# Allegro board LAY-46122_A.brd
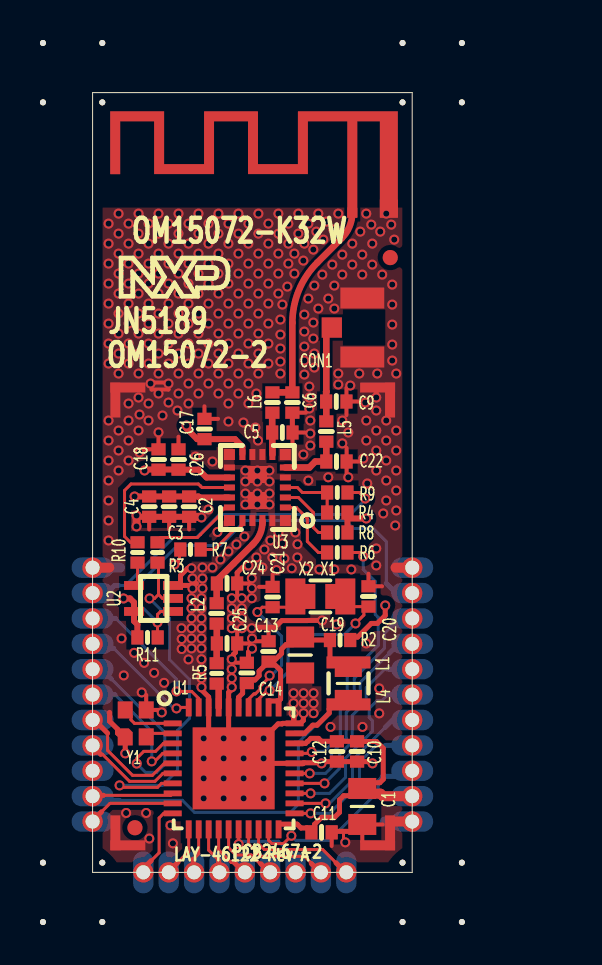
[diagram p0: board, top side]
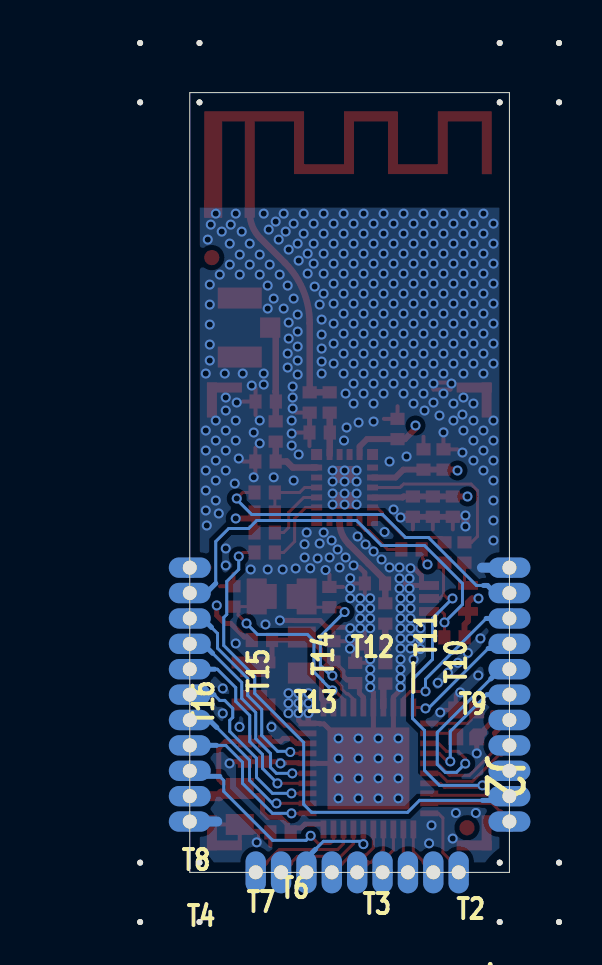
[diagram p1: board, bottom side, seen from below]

Outline 16 x 39 mm; copper layers: TOP, ANALOGUE GROUND, DIGITAL GROUND, BOTTOM. Coordinates in mm from the lower left corner of the outline.
Outline path: 0,39 0,0 16,0 16,39 0,39

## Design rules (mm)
constraint set DEFAULT: min track width 0.15
net group ALIM: nets N16830522 N16830755 VDD
net group DEFAUT: nets ANT_SEL CPS LA LB LNA_BYPASS N16830681 N16830775 N16832469 N16839365 N16842652 N16847933 N16848100 N16852723 N16876581 N169107841 PIO_0/SPI1_SCK PIO_1/SPI1_MISO PIO_2/SPI1_MOSI PIO_3/SPI1_SSELN0 PIO_4/RFTX PIO_5/RFRX PIO_6/PWM6-PD PIO_7/PWM7-PD PIO_8/USART0_TXD PIO_9/USART0_RXD PIO_10/I2C0_SCL PIO_11/I2C0_SDA PIO_12/SWCLK PIO_13/SWDIO PIO_14/ADC0 PIO_15/ADC1 PIO_16/SPIFI_CSN PIO_17/SPIFI_IO3 PIO_18/SPIFI_CLK PIO_19/SPIFI_IO0 PIO_20/SPIFI_IO2 PIO_21_SPIFI_IO1 RSTN
net group Z50: nets N16822568 N16830719 N16830729 N16831242 N16832450 N16869758 RF_PORT

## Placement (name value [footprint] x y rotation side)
1  BUBBLE-01  [BUBBLE_DIAM8]  23.5 23.5 0 top
ANT1  NC  [PCB_ANT_APPS]  13 33 0 top
C1  10uF  [C0805]  13.5 3.29 90 top
C2  1nF  [C0402]  4.83 18.29 270 top
C3  100nF  [C0402]  3.83 18.29 270 top
C4  4.7uF  [C0402]  2.83 18.29 270 top
C5  1pF  [C0402]  9.5 22 0 top
C6  1pF  [C0402]  10 23.5 270 top
C9  1pF  [C0402]  12.2 23.55 0 top
C10  100nF  [C0402]  13.24 6.04 90 top
C11  100nF  [C0402]  11.46 2 0 top
C12  47pF  [C0402]  12.23 6.04 90 top
C13  100nF  [C0402]  8.81 11.05 90 top
C14  47pF  [C0402]  7.72 9.97 90 top
C17  1nF  [C0402]  5.6 22.18 90 top
C18  100nF  [C0402]  3.3 20.65 90 top
C19  10uF  [C0805]  10.39 10.87 270 top
C20  NC  [C0402]  13.81 13.8 270 top
C21  NC  [C0402]  9.01 13.77 90 top
C22  1pF  [C0402]  12.21 20.55 0 top
C24  0.8pF  [C0402]  6.73 14.45 180 top
C25  2.0pF  [C0402]  6.73 11.45 180 top
C26  1nF  [C0402]  4.3 20.65 90 top
CON1  SMC_UFL  [SMC-UFL-R-SMT]  13.5 27.25 90 top
FID1  NC  [FID1]  2.12 2.23 0 top
FID2  NC  [FID1]  14.9 30.75 0 top
L1  4,7uH_NC  [IND_CB_2518_2520]  12.81 9.45 270 top
L2  2.9nH  [SELF_0402]  6.21 12.95 270 top
L4  4.7uH  [0805C_IPCC]  12.8 9.45 270 top
L5  2.7nH  [SELF_0402]  11.7 22.05 270 top
L6  2.7nH  [SELF_0402]  9 23.5 270 top
LY1  NC  [LYRE_31PTS_CARRIER]  0 12.7 0 top
NOREF  -  []  0 0 0 top
NOREF#2  -  [unnamed#2]  17 40 0 top
NOREF#3  -  [unnamed#2]  -1 -1 0 top
NOREF#4  -  []  0 0 90 top
NOREF#5  -  []  0 0 90 top
NOREF#6  -  []  0 39 0 top
NOREF#7  -  []  -76.6 -194.1 0 top
NOREF#8  -  []  4.08 29.77 0 top
NOREF#9  -  []  16.52 -165.47 0 top
NOREF#10  -  [unnamed#2]  17 -1 0 top
NOREF#11  -  [unnamed#2]  -1 40 0 top
R2  NC  [R0402]  12.39 11.62 0 top
R3  1K00  [R0402]  3.25 16 270 top
R4  47K0  [R0402]  12.25 18 180 top
R5  0R  [R0402]  6.21 9.95 270 top
R6  1K00  [R0402]  12.25 16 180 top
R7  1K00  [R0402]  4.9 16.15 0 top
R8  1K00  [R0402]  12.25 17 180 top
R9  1K00  [R0402]  12.25 19 180 top
R10  1K00  [R0402]  2.25 16 270 top
R11  47K0  [R0402]  2.75 11.75 0 top
SH1  SHIELD-13.7X22.9  [SHIELD_13MM7X22MM9]  1.14 1.35 0 top
U1  JN5189_40  [SOT618-1_HVQFN40_050_JN518X]  7.06 5.2 0 top
U2  74HC1G02  [SOT353]  3.05 13.7 90 top
U3  -  [SKY66112-11]  8.25 19.25 180 top
X1  32.768Khz_NC  [NX3215SA]  11.4 13.8 180 top
X2  32.768Khz  [NX2012SA]  11.4 13.8 180 top
Y1  32.000Mhz  [NX2016SA]  2.16 7.45 270 top

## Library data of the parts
1 = BUBBLE: alternate symbols: (BUBBLE_DIAM4)
ANT1 = ANTENNA_JN518x: alternate symbols: (pcb_ant_apps_flip)
C1 C19 = CAPA: alternate symbols: (0805C); tolerance: 10%
C2-C4 C10 C11 C13 C17 C18 C26 = CAPA: User Part Number: BCNNUMBER; Tolerance: 10%; alternate symbols: (0402C); tolerance: 10%
C5 C6 C9 C22 = CAPA: User Part Number: BCNNUMBER; Tolerance: +/-0.25pF; alternate symbols: (0402C); tolerance: +/-0.25pF
C12 C14 = CAPA: User Part Number: BCNNUMBER; Tolerance: 5%; alternate symbols: (0402C); tolerance: 5%
C20 C21 = CAPA: User Part Number: BCNNUMBER; Tolerance: -; alternate symbols: (0402C); tolerance: -
C24 C25 = CAPA: User Part Number: BCNNUMBER; Tolerance: +/-0.1pF; alternate symbols: (0402C); tolerance: +/-0.1pF
CON1 = SMC_UFL
FID1 FID2 = MIRE
L1 = SELF: Tolerance: TOLERANCE; User Part Number: PARTNUM
L2 L5 L6 = SELF: Tolerance: TOLERANCE; User Part Number: BCNNUMBER
L4 = SELF
LY1 = LYRE_MODJN518x_31PTS
R2 = RES: User Part Number: BCNNUMBER; Tolerance: -; tolerance: -
R3 R6-R10 = RES: User Part Number: BCNNUMBER; Tolerance: 5%; alternate symbols: (0402R); tolerance: 5%
R4 R11 = RES: User Part Number: BCNNUMBER; Tolerance: 1%; alternate symbols: (0402R); tolerance: 1%
R5 = RES: User Part Number: BCNNUMBER; Tolerance: -; alternate symbols: (0402R); tolerance: -
SH1 = SHIELD_8PTS
U1 = JN518x_QFN40: Tolerance: TOL; User Part Number: PN
U2 = 74HC1G02: Tolerance: TOLERANCE; User Part Number: PARTNUM
U3 = SKY66112-11: User Part Number: ***; Tolerance: ***
X1 X2 = XTAL
Y1 = XTAL_NX2016_4P

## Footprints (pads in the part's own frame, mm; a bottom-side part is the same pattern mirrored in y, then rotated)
0805C_IPCC
  rect 0.95x1.35 smd: 1(-0.8,0) 2(0.8,0)
BUBBLE_DIAM8
  round 0 smd: 1(0,0)
C0402
  rect 0.61x0.711 smd: 1(-0.508,0) 2(0.508,0)
C0805
  rect 1.05x1.4 smd: 1(-0.9,0) 2(0.9,0)
FID1
  round 0.76 smd: 1(0,0)
IND_CB_2518_2520
  rect 0.6x2.2 smd: 1(-1.05,0) 2(1.05,0)
LYRE_31PTS_CARRIER
  round 1.02 hole 0.7: 1(0,2.54) 2(0,1.27) 3(0,0) 4(0,-1.27) 5(0,-2.54) 6(0,-3.81) 7(0,-5.08) 8(0,-6.35) 9(0,-7.62) 10(0,-8.89) 11(0,-10.16) 12(2.54,-12.7) 13(3.81,-12.7) 14(5.08,-12.7) 15(6.35,-12.7) 16(7.62,-12.7) 17(8.89,-12.7) 18(10.16,-12.7) 19(11.43,-12.7) 20(12.7,-12.7) 21(16,-10.16) 22(16,-8.89) 23(16,-7.62) 24(16,-6.35) 25(16,-5.08) 26(16,-3.81) 27(16,-2.54) 28(16,-1.27) 29(16,0) 30(16,1.27) 31(16,2.54)
NX2012SA
  rect 1x1.25 smd: 1(-0.75,0) 2(0.75,0)
NX2016SA
  rect 0.85x0.75 smd: 1(-0.675,-0.525) 3(0.675,0.525) 4(-0.675,0.525)
  custom 0.188x0.188 smd: 2(0.675,-0.525)
NX3215SA
  rect 1x1.8 smd: 1(-1.25,0) 2(1.25,0)
PCB_ANT_APPS
  rect 0.9x0.9 smd: 1(1.829,0.2)
  rect 0.5x0.5 smd: 3(0,0)
R0402
  rect 0.61x0.711 smd: 1(-0.508,0) 2(0.508,0)
SELF_0402
  rect 0.61x0.711 smd: 1(-0.508,0) 2(0.508,0)
SHIELD_13MM7X22MM9
  rect 0.5x1.75 smd: 1(0,0.625) 4(13.75,0.625) 5(13.75,22.275) 8(0,22.275)
  rect 1.75x0.5 smd: 2(0.625,0) 3(13.125,0) 6(13.125,22.9) 7(0.625,22.9)
SKY66112-11
  rect 0.55x0.55 smd: 1(-1.4,1.65) 7(-1.4,-1.65) 12(1.4,-1.65) 18(1.4,1.65)
  rect 0.55x0.3 smd: 2(-1.4,1) 3(-1.4,0.5) 4(-1.4,0) 5(-1.4,-0.5) 6(-1.4,-1) 13(1.4,-1) 14(1.4,-0.5) 15(1.4,0) 16(1.4,0.5) 17(1.4,1)
  rect 0.3x0.55 smd: 8(-0.75,-1.65) 9(-0.25,-1.65) 10(0.25,-1.65) 11(0.75,-1.65) 19(0.75,1.65) 20(0.25,1.65) 21(-0.25,1.65) 22(-0.75,1.65)
  rect 1x0.85 smd: 23(0,0.65) 24(0,-0.65)
SMC-UFL-R-SMT
  rect 1.016x1.016 smd: 1(0,1.525)
  rect 1.05x2.2 smd: 2(-1.475,0) 3(1.475,0)
SOT353
  rect 0.44x1 smd: 1(-0.65,-0.975) 2(0,-0.975) 3(0.65,-0.975) 4(0.65,0.975) 5(-0.65,0.975)
SOT618-1_HVQFN40_050_JN518X
  rect 0.9x0.29 smd: 1(-3.05,2.25) 2(-3.05,1.75) 3(-3.05,1.25) 4(-3.05,0.75) 5(-3.05,0.25) 6(-3.05,-0.25) 7(-3.05,-0.75) 8(-3.05,-1.25) 9(-3.05,-1.75) 10(-3.05,-2.25) 21(3.05,-2.25) 22(3.05,-1.75) 23(3.05,-1.25) 24(3.05,-0.75) 25(3.05,-0.25) 26(3.05,0.25) 27(3.05,0.75) 28(3.05,1.25) 29(3.05,1.75) 30(3.05,2.25)
  rect 0.29x0.9 smd: 11(-2.25,-3.05) 12(-1.75,-3.05) 13(-1.25,-3.05) 14(-0.75,-3.05) 15(-0.25,-3.05) 16(0.25,-3.05) 17(0.75,-3.05) 18(1.25,-3.05) 19(1.75,-3.05) 20(2.25,-3.05) 31(2.25,3.05) 32(1.75,3.05) 33(1.25,3.05) 34(0.75,3.05) 35(0.25,3.05) 36(-0.25,3.05) 37(-0.75,3.05) 38(-1.25,3.05) 39(-1.75,3.05) 40(-2.25,3.05)
  rect 4.1x4.1 smd: 41(0,0)
unnamed#2
  round 0.3 hole 0.4 unplated: (-1.485,1.485) (-1.485,-1.485) (1.485,1.485) (1.485,-1.485)

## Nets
GND: ANT1.1 C1.1 C2.2 C3.2 C4.2 C5.2 C6.2 C9.2 C10.1 C11.2 C12.1 C13.2 C14.2 C17.2 C18.2 C19.2 C20.1 C21.2 C22.2 C24.1 C25.1 C26.2 CON1.2 CON1.3 LY1.1 LY1.21 LY1.31 SH1.1 SH1.2 SH1.3 SH1.4 SH1.5 SH1.6 SH1.7 SH1.8(GND#8) U1.26 U1.30 U1.36 U1.38 U1.41 U2.3 U3.1 U3.5 U3.7 U3.9 U3.10 U3.12 U3.13 U3.18 U3.20 U3.22 U3.23 U3.24 Y1.2 Y1.4
VDD: C1.2 C2.1 C3.1 C4.1 C10.2 C11.1 C12.2 C17.1 C18.1 C26.1 LY1.22(VDD) R2.2 R4.1 R7.1 R8.1 R11.1 U1.20 U1.28 U2.5 U3.11(VDD) U3.14 U3.16
ANT_SEL: LY1.2 R9.1
CPS: R10.2 U2.4(Y)
LA: LY1.4 U1.40
LB: LY1.3 U1.39
LNA_BYPASS: LY1.30 R11.2 U2.1
PIO_0/SPI1_SCK: LY1.5 U1.3
PIO_1/SPI1_MISO: LY1.6 U1.4
PIO_2/SPI1_MOSI: LY1.7 U1.5
PIO_3/SPI1_SSELN0: LY1.8 U1.6
PIO_4/RFTX: R3.2 U1.7 U2.2
PIO_5/RFRX: LY1.10 R6.1 U1.8
PIO_6/PWM6-PD: LY1.11 U1.9
PIO_7/PWM7-PD: LY1.12 U1.10
PIO_8/USART0_TXD: LY1.13 U1.11
PIO_9/USART0_RXD: LY1.14 U1.12
PIO_10/I2C0_SCL: LY1.15 U1.13
PIO_11/I2C0_SDA: LY1.16 U1.14
PIO_12/SWCLK: LY1.17 U1.15
PIO_13/SWDIO: LY1.18 U1.16
PIO_14/ADC0: LY1.19 U1.17
PIO_15/ADC1: LY1.20 U1.18
PIO_16/SPIFI_CSN: LY1.23 U1.19
PIO_17/SPIFI_IO3: LY1.24 U1.21
PIO_18/SPIFI_CLK: LY1.25 U1.22
PIO_19/SPIFI_IO0: LY1.26 U1.23
PIO_20/SPIFI_IO2: LY1.27 U1.24
PIO_21_SPIFI_IO1: LY1.28 U1.25
RF_PORT: C24.2 L2.1 U3.21
RSTN: LY1.29 U1.27
N16822568: C5.1 L6.2 U3.8
N16830522: L1.2 L4.2 U1.29
N16830681: U1.1(XTAL_P) Y1.1
N16830719: C25.2 L2.2 R5.1
N16830729: R5.2 U1.37
N16830755: C13.1 C14.1 C19.1 L1.1 L4.1 R2.1 U1.31 U1.32 U1.35
N16830775: C20.2 U1.33 X1.1 X2.1
N16831242: C22.1 L5.2 U3.6
N16832450: C9.1 CON1.1 L5.1
N16832469: C21.1 U1.34 X1.2 X2.2
N16839365: R3.1 U3.17
N16842652: U1.2 Y1.3
N16847933: R8.2 U3.3
N16848100: R10.1 U3.15
N16852723: R6.2 U3.2
N16869758: ANT1.3(IN) C6.1 L6.1
N16876581: R4.2 R9.2 U3.4
N169107841: R7.2 U3.19

Pads without a net: 1 1; FID1 1; FID2 1; LY1 9

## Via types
v1: diameter 0.5, hole 0.31, TOP to BOTTOM, 460 vias

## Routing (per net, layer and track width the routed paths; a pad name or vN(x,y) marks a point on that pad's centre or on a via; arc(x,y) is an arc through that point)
GND: length 64
  TOP w0.15: 12.56,2.05 12.56,1.59 v1(12.65,1.5)
  TOP w0.2: 13.81,14.94 C20.1 14.49,14.31 ; C9.2 13.34,23.55 ; C9.2 12.71,22.87 ; C9.2 12.71,24.23 ; 2.69,8.88 Y1.4 3.39,8.12 ; 3.3,21.79 C18.2 2.62,21.16 ; 10.01,21.32 C5.2 10.64,22 ; 4.83,17.15 C2.2 ; 7.04,10.48 C14.2 ; C6.2 10.68,22.99 ; 9.01,14.91 C21.2 8.33,14.28 ; 7.24,13.77 C24.1 7.87,14.45 ; 13.5,1.54 C1.1 14.53,2.4 ; 2.83,17.15 C4.2 ; C26.2 4.3,21.79 ; 3.83,17.15 C3.2 ; 7.87,11.45 C25.1 7.24,12.13 ; 6.28,22.68 C17.2 5.6,23.31 ; 8.81,12.19 C13.2 8.13,11.56 ; U1.30 10.11,7.92 ; 12.72,19.87 C22.2 ; C22.2 12.72,21.23 ; C22.2 13.35,20.55 ; 11.97,1.32 C11.2
  TOP w0.25: 10.06,7.45 U1.30 10.4,7.45 10.55,7.6 10.55,7.95 v1(10.56,7.96) ; 10.06,7.45 v1(10.06,7.96) ; 10.06,7.45 9.51,7.45 9.49,7.42 9.29,7.42 8.81,6.95 ; v1(11.46,5.45) 11.55,5.54 C12.1 C10.1 13.92,5.54 v1(14.01,5.45) ; v1(11.46,5.45) 11.43,5.48 10.58,5.48 10.55,5.45 U1.26 8.81,5.45 ; v1(11.46,5.45) 11.5,5.41 ; 4.03,14.35 4.4,14.35 ; 4.4,14.35 4.4,14.85 4.76,15.21 v1(4.95,15.21) 4.95,15.2 ; 4.4,14.35 5.1,14.35 5.2,14.45 ; 5.81,6.95 U1.38 5.81,8.77 5.45,9.13 v1(5.45,9.26) ; 7.5,15.25 7.24,14.99 C24.1 ; C5.2 10,22.01 C6.2 ; 13.55,2.27 13.23,2.27 13.01,2.05 12.02,2.05 C11.2 ; v1(7.98,11.19) 7.8,11.01 7.8,10.54 7.72,10.46 ; v1(6.97,10.66) 7.05,10.74 7.05,10.9 7.15,11 7.15,11.36 C25.1 ; v1(7.97,12.21) 8.02,12.26 9.14,12.26 9.47,12.6 10.77,12.6 10.78,12.6 v1(11.49,12.6) ; SH1.6 14.2,24.1 v1(14.2,23.75) ; 6.81,6.95 U1.36 6.81,9 6.97,9.16 v1(6.97,9.26) ; v1(1.64,5.95) Y1.2 1.44,6.78 1.25,6.96 1.25,7.16 0.85,7.56 0.85,8
  TOP w0.3: v1(2.2,17.85) 2.27,17.78 C4.2 C3.2 C2.2
  TOP w0.4: v1(2.2,17.85) v1(2.2,17.3) ; v1(5.45,17.75) 5.42,17.78 C2.2
  TOP w0.5: LY1.1 0.84,15.24 ; 15.16,2.54 LY1.21 ; 15.16,15.24 LY1.31
  ANALOGUE GROUND w0.5: 15.21,2.54 LY1.21 ; LY1.1 0.79,15.24 ; 15.21,15.24 LY1.31
  DIGITAL GROUND w0.5: 15.21,2.54 LY1.21 ; LY1.1 0.79,15.24
  BOTTOM w0.5: LY1.1 1.38,15.24 ; 14.62,2.54 LY1.21
  vias: v1(0.8,32.45) v1(0.8,31.45) v1(0.8,30.45) v1(0.8,29.45) v1(0.8,28.45) v1(0.8,27.45) v1(0.8,26.45) v1(0.8,25.45) v1(0.8,22.6) v1(0.8,21.6) v1(0.8,20.6) v1(0.8,19.6) v1(0.8,18.6) v1(0.8,17.6) v1(0.8,16.6) v1(1.3,32.95) v1(1.3,31.95) v1(1.3,30.95) v1(1.3,29.95) v1(1.3,28.95) v1(1.3,27.95) v1(1.3,26.95) v1(1.3,25.95) v1(1.3,24.95) v1(1.3,22.1) v1(1.3,21.1) v1(1.3,20.1) v1(1.45,11.7) v1(1.56,9.85) v1(1.68,2.97) v1(1.8,32.45) v1(1.8,31.45) v1(1.8,30.45) v1(1.8,29.45) v1(1.8,28.45) v1(1.8,27.45) v1(1.8,26.45) v1(1.8,25.45) v1(1.8,23.45) v1(1.8,22.6) v1(1.8,21.6) v1(1.8,20.6) v1(2.08,10.98) v1(2.3,32.95) v1(2.3,31.95) v1(2.3,30.95) v1(2.3,29.95) v1(2.3,28.95) v1(2.3,27.95) v1(2.3,26.95) v1(2.3,25.95) v1(2.3,24.95) v1(2.3,23.75) v1(2.3,22.1) v1(2.35,22.9) v1(2.35,21) v1(2.46,9) v1(2.58,10.48) v1(2.68,2.97) v1(2.8,32.45) v1(2.8,31.45) v1(2.8,30.45) v1(2.8,29.45) v1(2.8,28.45) v1(2.8,27.45) v1(2.8,26.45) v1(2.8,25.45) v1(2.8,23.45) v1(2.8,22.6) v1(2.84,1.69) v1(2.9,24.45) v1(3.08,9.98) v1(3.3,32.95) v1(3.3,31.95) v1(3.3,30.95) v1(3.3,29.95) v1(3.3,28.95) v1(3.3,27.95) v1(3.3,26.95) v1(3.3,25.95) v1(3.3,24.95) v1(3.3,23.95) v1(3.3,22.01) v1(3.5,22.85) v1(3.46,8) v1(3.58,9.48) v1(3.8,32.45) v1(3.8,31.45) v1(3.8,30.45) v1(3.8,29.45) v1(3.8,28.45) v1(3.8,27.45) v1(3.8,26.45) v1(3.8,25.45) v1(3.8,24.45) v1(3.8,23.5) v1(3.9,2.35) v1(4.02,1.45) v1(4.25,23.1) v1(4.3,32.95) v1(4.3,31.95) v1(4.3,30.95) v1(4.3,29.95) v1(4.3,28.95) v1(4.3,27.95) v1(4.3,26.95) v1(4.3,25.95) v1(4.3,24.95) v1(4.3,23.95) v1(4.45,12.21) v1(4.46,11.67) v1(4.46,11.17) v1(4.8,32.45) v1(4.8,31.45) v1(4.8,30.45) v1(4.8,29.45) v1(4.8,28.45) v1(4.8,27.45) v1(4.8,26.45) v1(4.8,25.45) v1(4.8,24.45) v1(4.8,23.45) v1(4.8,10.65) v1(5,14.7) v1(5,14.2) v1(4.95,13.71) v1(4.95,13.21) v1(4.95,12.71) v1(4.95,12.21) v1(4.95,11.7) v1(4.95,11.2) v1(5.15,20.8) v1(5.3,32.95) v1(5.3,31.95) v1(5.3,30.95) v1(5.3,29.95) v1(5.3,28.95) v1(5.3,27.95) v1(5.3,26.95) v1(5.3,25.95) v1(5.3,24.95) v1(5.3,23.95) v1(5.5,15.25) v1(5.5,14.7) v1(5.5,14.2) v1(5.45,13.71) v1(5.45,13.21) v1(5.45,12.71) v1(5.45,12.21) v1(5.45,11.7) v1(5.45,11.2) v1(5.45,10.66) v1(5.45,10.16) v1(5.45,9.71) v1(5.56,6.7) v1(5.56,5.7) v1(5.56,4.7) v1(5.56,3.7) v1(5.8,32.45) v1(5.8,31.45) v1(5.8,30.45) v1(5.8,29.45) v1(5.8,28.45) v1(5.8,27.45) v1(5.8,26.45) v1(5.8,25.45) v1(5.8,24.45) v1(5.8,18.15) v1(6,20.55) v1(6,15.25) v1(6.25,17.02) v1(6.3,32.95) v1(6.3,31.95) v1(6.3,30.95) v1(6.3,29.95) v1(6.3,28.95) v1(6.3,27.95) v1(6.3,26.95) v1(6.3,25.95) v1(6.3,24.95) v1(6.3,23.95) v1(6.4,15.65) v1(6.56,6.7) v1(6.56,5.7) v1(6.56,4.7) v1(6.56,3.7) v1(6.8,32.45) v1(6.8,31.45) v1(6.8,30.45) v1(6.8,29.45) v1(6.8,28.45) v1(6.8,27.45) v1(6.8,26.45) v1(6.8,25.45) v1(6.8,24.45) v1(6.8,23.45) v1(6.8,22.55) v1(6.8,16.05) v1(6.97,13.71) v1(6.97,13.21) v1(6.97,12.71) v1(6.97,12.21) v1(6.97,10.16) v1(6.97,9.71) v1(7.2,16.4) v1(7.3,32.95) v1(7.3,31.95) v1(7.3,30.95) v1(7.3,29.95) v1(7.3,28.95) v1(7.3,27.95) v1(7.3,26.95) v1(7.3,25.95) v1(7.3,24.95) v1(7.3,23.95) v1(7.55,22.5) v1(7.47,13.71) v1(7.47,13.21) v1(7.47,12.71) v1(7.47,12.21) v1(7.6,16.8) v1(7.56,6.7) v1(7.56,5.7) v1(7.56,4.7) v1(7.56,3.7) v1(7.65,20.1) v1(7.65,19.55) v1(7.65,18.95) v1(7.65,18.4) v1(7.8,32.45) v1(7.8,31.45) v1(7.8,30.45) v1(7.8,29.45) v1(7.8,28.45) v1(7.8,27.45) v1(7.8,26.45) v1(7.8,25.45) v1(7.8,24.45) v1(7.8,23.45) v1(7.8,15.35) v1(7.97,14.71) v1(7.97,14.21) v1(7.97,13.71) v1(7.98,11.69) v1(8.2,23.95) v1(8.15,22.25) v1(8.25,20.1) v1(8.25,19.55) v1(8.25,18.95) v1(8.25,18.4) v1(8.2,15.75) v1(8.3,32.95) v1(8.3,31.95) v1(8.3,30.95) v1(8.3,29.95) v1(8.3,28.95) v1(8.3,27.95) v1(8.3,26.95) v1(8.3,25.95) v1(8.3,24.95) v1(8.28,21.6) v1(8.5,15.25) v1(8.6,16.15) v1(8.56,6.7) v1(8.56,5.7) v1(8.56,4.7) v1(8.56,3.7) v1(8.8,32.45) v1(8.8,31.45) v1(8.8,30.45) v1(8.8,29.45) v1(8.8,28.45) v1(8.8,27.45) v1(8.8,26.45) v1(8.8,25.45) v1(8.85,20.1) v1(8.85,19.55) v1(8.85,18.95) v1(8.85,18.4) v1(8.9,16.6) v1(9,15.75) v1(9.2,15.12) v1(9.3,32.95) v1(9.3,31.95) v1(9.3,30.95) v1(9.3,29.95) v1(9.3,28.95) v1(9.3,17) v1(9.4,27.65) v1(9.4,26.9) v1(9.4,26.2) v1(9.4,25.55) v1(9.4,24.95) v1(9.5,28.4) v1(9.5,16.45) v1(9.6,15.7) v1(9.8,32.45) v1(9.8,31.45) v1(9.8,30.45) v1(9.75,29.3) v1(9.97,15.21) v1(10.1,30.95) v1(10.1,29.95) v1(10.06,8.96) v1(10.06,8.46) v1(10.15,17) v1(10.25,15.75) v1(10.3,32.95) v1(10.3,31.95) v1(10.26,16.41) v1(10.6,31.45) v1(10.55,30.6) v1(10.6,27.9) v1(10.6,27.05) v1(10.6,26.3) v1(10.6,25.6) v1(10.6,24.9) v1(10.55,20.9) v1(10.56,8.96) v1(10.56,8.46) v1(10.7,15.2) v1(10.8,32.45) v1(10.8,28.7) v1(10.85,24.3) v1(10.85,23.75) v1(10.85,23.2) v1(10.8,19.6) v1(10.9,22.6) v1(10.9,21.95) v1(10.9,21.35) v1(11.05,31.15) v1(11.1,29.35) v1(11.05,27.5) v1(11.05,26.7) v1(11.1,25.95) v1(11.1,25.25) v1(11.06,8.96) v1(11.06,8.46) v1(11.06,7.96) v1(11.2,32.05) v1(11.3,32.95) v1(11.3,28.2) v1(11.35,15.15) v1(11.5,29.9) v1(11.55,31.65) v1(11.7,32.55) v1(11.8,28.7) v1(11.8,19.76) v1(11.91,7.28) v1(12,30.4) v1(12.05,32.15) v1(12.1,29.35) v1(12.1,28.2) v1(12.1,15.15) v1(12.21,12.4) v1(12.3,32.95) v1(12.3,24.95) v1(12.3,24.4) v1(12.5,30.9) v1(12.5,29.9) v1(12.5,22.6) v1(12.5,21.46) v1(12.8,22) v1(12.8,19.76) v1(12.9,24.35) v1(12.95,15.15) v1(13,31.45) v1(13,30.4) v1(13.35,24.95) v1(13.4,32.05) v1(13.5,30.9) v1(13.5,29.9) v1(13.51,7.28) v1(13.55,20.7) v1(13.7,32.95) v1(13.65,23.5) v1(13.7,22.6) v1(13.7,21.6) v1(13.7,11.45) v1(13.75,19.45) v1(13.95,32.4) v1(14,31.45) v1(14,30.4) v1(14.25,24.95) v1(14.2,23.1) v1(14.2,22.1) v1(14.2,21.1) v1(14.2,20.1) v1(14.2,16.2) v1(14.2,15.35) v1(14.35,9.2) v1(14.35,7.95) v1(14.4,32.05) v1(14.5,29.9) v1(14.55,17.95) v1(14.7,32.95) v1(14.7,22.6) v1(14.7,21.6) v1(14.7,20.6) v1(14.7,19.6) v1(14.7,18.6) v1(14.95,32.4) v1(15,29.4) v1(15,28.4) v1(15,27.4) v1(15,26.4) v1(15,25.6) v1(15.1,31.65) v1(15.2,24.95) v1(15.2,22.1) v1(15.2,21.1) v1(15.2,20.1) v1(15.2,19.1) v1(15.2,18.1) v1(15.15,17.35)
VDD: length 78
  TOP w0.15: v1(4.1,15.4) 4.27,15.4 4.3,15.43 4.3,15.65 4.35,15.7 4.35,16.15 R7.1 ; LY1.22 15.96,3.81
  TOP w0.25: 13.84,4.49 13.79,4.49 C1.2 ; 13.84,4.49 13.55,4.2 C1.2 ; 13.84,4.49 14.38,4.49 14.55,4.66 14.55,6.21 14.21,6.54 13.25,6.54 C10.2 C12.2 11.46,6.55 11.31,6.7 10.93,6.7 10.78,6.55 10.76,6.55 10.66,6.45 U1.28 ; C1.2 13.32,4.2 12.96,3.83 12.57,3.83 12.36,3.62 12.36,3 12.11,2.75 11.46,2.75 11.11,2.4 11.11,2.16 C11.1 10.73,2.22 10.43,2.22 10.24,2.41 9.31,2.41 U1.20 ; v1(14.65,13.35) 14.65,12.85 14.25,12.45 13.95,12.45 13.27,11.77 13.05,11.77 R2.2
  TOP w0.3: R11.1 2.24,12.4 2.08,12.57 2.08,13.5 1.88,13.7 v1(1.55,13.7) ; U3.14 5.7,19.75 5.31,20.14 C26.1 4.29,20.15 3.31,20.15 ; C18.1 3.31,20.15 ; 3.31,20.15 2.65,20.15 v1(2.6,20.1) ; R8.1 12.76,17.7 ; 12.76,17.7 v1(13.7,17.7) ; 12.76,17.7 R4.1 ; U3.16 5.35,18.75 5.3,18.8 C2.1 C3.1 C4.1 v1(2.1,18.8) ; U3.11 7.5,21.3 7.13,21.67 C17.1 5.23,21.67 4.7,22.2 v1(4.7,22.35)
  TOP w0.5: 15.96,3.81 14.54,3.81 14.41,3.94 13.76,3.94 ; 13.76,3.94 C1.2 ; 13.76,3.94 13.71,3.94 13.45,4.2
  DIGITAL GROUND w0.5: 4.14,19.55 4.14,18.85 ; 4.14,19.55 5.5,19.55 7.35,17.7 v1(13.7,17.7) 13.75,17.7 14.9,16.55 14.9,13.6 v1(14.65,13.35) 15.05,12.95 15.05,4.6 15.84,3.81 LY1.22 ; 4.14,19.55 4.14,20.1 ; 4.14,18.85 2.15,18.85 v1(2.1,18.8) ; 4.14,18.85 4.1,18.8 v1(4.1,15.4) 2.85,15.4 1.55,14.1 v1(1.55,13.7) ; v1(4.7,22.35) 4.14,21.8 4.14,20.1 ; 4.14,20.1 v1(2.6,20.1)
ANT_SEL: length 16.7
  TOP w0.15: v1(13.65,18.7) 13.35,19 R9.1
  BOTTOM w0.15: v1(13.65,18.7) 13.65,18.65 12.9,17.9 6.35,17.9 5.2,16.75 4.05,16.75 1.65,14.35 1.3,14.35
  BOTTOM w0.25: 1.3,14.35 1.1,14.35 0.72,13.97 LY1.2
CPS: length 1.2
  TOP w0.15: R10.2 2.25,14.53 2.08,14.35
LA: length 6.2
  TOP w0.15: U1.40 4.25,8.25 v1(4.2,8.2)
  BOTTOM w0.15: LY1.4 -0.04,11.43 ; 1.06,11.2 4.06,8.2 v1(4.2,8.2)
  BOTTOM w0.25: 1.06,11.2 0.19,11.2 -0.04,11.43
LB: length 7.8
  TOP w0.15: U1.39 5.31,8.7 4.96,9.05 v1(4.2,9.05)
  BOTTOM w0.15: 1.16,12.7 4.2,9.66 v1(4.2,9.05)
  BOTTOM w0.25: 1.16,12.7 LY1.3
LNA_BYPASS: length 22
  TOP w0.15: R11.2 3.25,11.76 v1(3.25,12.5) 3.25,12.9 3.4,13.05 4.03,13.05
  BOTTOM w0.15: v1(3.25,12.5) 2.35,13.4 2.35,14.45 4.25,16.35 6.4,16.35 7.65,17.6 12.65,17.6 13.05,17.2 14.05,17.2 14.7,16.55 14.7,14.45
  BOTTOM w0.25: 14.7,14.45 15.18,13.97 LY1.30
PIO_0/SPI1_SCK: length 10.7
  TOP w0.15: v1(2.21,5.44) 2.21,5.7 2.56,6.05 3.15,6.05 3.55,6.45 U1.3
  BOTTOM w0.15: 0.94,9.68 3.61,7 3.61,5.4 3.21,5 2.65,5 v1(2.21,5.44)
  BOTTOM w0.25: -0.04,10.16 LY1.5 0.45,10.16 0.94,9.68
PIO_1/SPI1_MISO: length 6.5
  TOP w0.15: v1(2.96,5.55) 3.11,5.55 3.51,5.95 U1.4
  BOTTOM w0.15: v1(2.96,5.55) 2.96,7.05 1.12,8.89
  BOTTOM w0.25: -0.04,8.89 LY1.6 1.12,8.89
PIO_2/SPI1_MOSI: length 5.9
  TOP w0.15: U1.5 3.59,5.45 2.99,4.85 2,4.85 0.75,6.1 0.75,6.96
  TOP w0.25: LY1.7 0.09,7.62 0.75,6.96
PIO_3/SPI1_SSELN0: length 5
  TOP w0.15: U1.6 3.52,4.95 3.12,4.55 1.85,4.55 0.5,5.9 0.41,5.9 ; -0.04,6.35 LY1.8
  TOP w0.25: 0.41,5.9 -0.04,6.35
PIO_4/RFTX: length 18.6
  TOP w0.15: U1.7 3.45,4.45 3.25,4.25 1.45,4.25 v1(1.35,4.35) ; 3.3,13.9 3.1,13.7 v1(2.85,13.7) ; 3.3,13.9 3.3,15.44 R3.2 ; 3.3,13.9 3.5,13.7 4.03,13.7
  BOTTOM w0.15: v1(1.35,4.35) 3.5,4.35 4.25,5.1 4.25,7.1 4.85,7.7 4.85,9.65 3.85,10.65 3.85,12.7 v1(2.85,13.7)
PIO_5/RFRX: length 30.2
  TOP w0.15: R6.1 13.35,16 v1(13.55,15.8) ; 0.55,3.85 3.91,3.85 U1.8 ; LY1.10 -0.04,3.81
  TOP w0.25: 0.55,3.85 0,3.85 -0.04,3.81
  BOTTOM w0.15: v1(13.55,15.8) 13.55,15.15 14.15,14.55 14.15,12.9 14.3,12.75 14.3,11.35 12.75,9.8 12.75,8.95 10.3,6.5 10.3,3.4 9.9,3 5.1,3 4.5,3.6 1.35,3.6
  BOTTOM w0.25: LY1.10 0.69,3.81 0.9,3.6 1.35,3.6
PIO_6/PWM6-PD: length 4.5
  TOP w0.15: LY1.11 -0.04,2.54 ; U1.9 0.87,3.45 0.45,3.02
  TOP w0.25: -0.04,2.54 0.45,3.02
PIO_7/PWM7-PD: length 3.9
  TOP w0.15: LY1.12 2.5,0 ; 2.93,0.58 3.33,0.98 3.33,2.72 3.56,2.95 U1.10
  TOP w0.25: 2.93,0.58 2.5,0.15 2.5,0
PIO_8/USART0_TXD: length 2.6
  TOP w0.15: U1.11 4.81,1.04 4.28,0.51 ; LY1.13 3.77,0
  TOP w0.25: 3.77,0 4.28,0.51
PIO_9/USART0_RXD: length 2.3
  TOP w0.15: 5.04,0.66 5.31,0.93 U1.12 ; LY1.14 5.04,0
  TOP w0.25: 5.04,0 5.04,0.66
PIO_10/I2C0_SCL: length 2.4
  TOP w0.15: U1.13 5.81,1.11 6.31,0.61 ; LY1.15 6.31,0
  TOP w0.25: 6.31,0 6.31,0.61
PIO_11/I2C0_SDA: length 2.8
  TOP w0.15: 7.09,0.49 6.94,0.49 6.31,1.12 U1.14 ; LY1.16 7.58,0
  TOP w0.25: 7.58,0 7.09,0.49
PIO_12/SWCLK: length 3.5
  TOP w0.15: U1.15 6.81,1.23 7.17,0.87 7.94,0.87 8.39,0.42 8.43,0.42 ; 8.85,0 LY1.17 8.9,0.01
  TOP w0.25: 8.85,0 8.43,0.42
PIO_13/SWDIO: length 4.7
  TOP w0.15: U1.16 v1(7.31,1.41)
  BOTTOM w0.15: LY1.18 10.12,0 ; 9.71,1.15 9.31,1.55 7.45,1.55 v1(7.31,1.41)
  BOTTOM w0.25: 10.12,0 10.12,0.74 9.71,1.15
PIO_14/ADC0: length 4.9
  TOP w0.15: LY1.19 11.39,0 ; U1.17 7.81,1.43 8.44,0.8 10.61,0.8 10.95,0.46 10.95,0.44
  TOP w0.25: 11.39,0 10.95,0.44
PIO_15/ADC1: length 5.7
  TOP w0.15: 12.19,0.47 11.52,1.14 8.6,1.14 8.31,1.43 U1.18 ; LY1.20 12.66,0
  TOP w0.25: 12.66,0 12.19,0.47
PIO_16/SPIFI_CSN: length 9.8
  TOP w0.15: v1(9.95,1.83) 9.56,1.44 8.97,1.44 8.81,1.6 U1.19
  BOTTOM w0.15: 15.96,5.08 LY1.23 ; 14.5,4.8 14.3,4.6 14.3,4.05 11.85,1.6 10.18,1.6 v1(9.95,1.83)
  BOTTOM w0.25: 15.96,5.08 15.68,4.8 14.5,4.8
PIO_17/SPIFI_IO3: length 7.9
  TOP w0.15: U1.21 v1(10.91,2.95)
  BOTTOM w0.15: v1(10.91,2.95) 11.86,2.95 13.36,4.45 13.36,5.51 14.2,6.35 14.66,6.35 ; 15.96,6.35 LY1.24
  BOTTOM w0.25: 14.66,6.35 15.96,6.35
PIO_18/SPIFI_CLK: length 8.2
  TOP w0.15: U1.22 v1(11.66,3.45)
  BOTTOM w0.15: LY1.25 15.96,7.62 ; 14.65,7.25 13.01,5.61 13.01,4.6 11.86,3.45 v1(11.66,3.45)
  BOTTOM w0.25: 14.65,7.25 15.02,7.62 15.96,7.62
PIO_19/SPIFI_IO0: length 9.4
  TOP w0.15: U1.23 v1(10.91,3.95)
  BOTTOM w0.15: v1(10.91,3.95) 11.86,3.95 12.66,4.75 12.66,5.71 14,7.05 14,7.6 13.85,7.75 13.85,8.2 14.25,8.6 14.5,8.6 14.79,8.89 ; LY1.26 15.96,8.89
  BOTTOM w0.25: 15.96,8.89 14.79,8.89
PIO_20/SPIFI_IO2: length 9.8
  TOP w0.15: v1(11.61,4.45) U1.24
  BOTTOM w0.15: 14.76,10.16 14.62,10.16 13.7,9.24 13.7,8.55 13,7.85 13,6.54 12.36,5.9 12.36,5.2 v1(11.61,4.45) ; 15.96,10.16 LY1.27
  BOTTOM w0.25: 14.76,10.16 15.96,10.16
PIO_21_SPIFI_IO1: length 10.2
  TOP w0.15: U1.25 v1(10.87,4.95)
  BOTTOM w0.15: LY1.28 15.96,11.43 ; 14.86,10.96 13.4,9.5 13.4,8.7 12.7,8 12.7,6.69 11.96,5.95 11.96,5.25 11.66,4.95 v1(10.87,4.95)
  BOTTOM w0.25: 15.96,11.43 15.33,11.43 14.86,10.96
RF_PORT: length 5
  TOP w0.33: L2.1 6.21,14.44 C24.2 6.22,14.45 arc(6.25,14.59) 6.33,14.71 7.06,15.44 7.99,16.38 arc(8.03,16.41) 8.06,16.45 arc(8.39,16.94) 8.5,17.51 U3.21
RSTN: length 10.4
  TOP w0.15: U1.27 10.9,5.95 v1(10.97,6.02)
  BOTTOM w0.15: 14.91,12.25 14.61,11.95 14.61,11.21 13.1,9.7 13.1,8.85 12.4,8.15 12.4,6.85 11.6,6.05 11,6.05 v1(10.97,6.02) ; LY1.29 15.96,12.7
  BOTTOM w0.25: 14.91,12.25 15.36,12.7 15.96,12.7
N16822568: length 2.1
  TOP w0.33: U3.8 C5.1 8.99,22.98 L6.2
N16830522: length 3.4
  TOP w0.25: U1.29 10.61,6.95 11.02,7.36 11.24,7.36 11.85,7.96 11.85,8.18 12.06,8.4 L1.2
N16830681: length 2.8
  TOP w0.15: Y1.1 1.92,7.84 1.92,7.63 2.1,7.45 U1.1
N16830719: length 2
  TOP w0.33: L2.2 6.22,12.43 6.22,11.45 ; 6.22,11.45 6.22,11.45 6.21,11.44 R5.1 ; 6.22,11.45 C25.2
N16830729: length 1.2
  TOP w0.33: U1.37 6.31,9.34 R5.2
N16830755: length 12.1
  TOP w0.25: L1.1 12.06,10.5 11.88,10.68 R2.1 10.54,11.62 C19.1 10.01,11.39 9.68,11.39 9.46,11.17 9.46,10.95 9.05,10.54 8.97,10.54 ; 9.31,8.57 8.81,8.57 U1.32 ; 9.31,8.57 U1.31 ; 9.31,8.57 9.41,8.67 9.41,10.1 8.97,10.54 ; U1.35 7.31,8.76 7.51,8.96 7.51,9.26 7.87,9.62 8.13,9.62 8.34,9.83 8.34,10.07 C13.1 8.97,10.54
N16830775: length 10.3
  TOP w0.15: v1(13.16,12.45) 13.58,12.87 13.58,13.06 C20.2 13.01,13.29 12.65,13.65 X1.1 ; U1.33 8.31,8.66 8.75,9.1 v1(8.86,9.1)
  BOTTOM w0.15: v1(13.16,12.45) 12.61,11.9 10.11,11.9 9.79,11.57 9.79,10.03 9.34,9.57 9.34,9.55 9.06,9.28 9.04,9.28 v1(8.86,9.1)
N16831242: length 3.2
  TOP w0.33: U3.6 10.85,20.25 11.15,20.55 C22.1 L5.2
N16832450: length 4.8
  TOP w0.33: L5.1 11.7,23.54 C9.1 11.69,23.6 ; 11.7,23.59 11.69,23.6 ; 11.69,23.6 11.69,24.04 11.7,24.05 11.7,26.98 CON1.1
N16832469: length 8.3
  TOP w0.15: X1.2 10.15,13.7 9.71,13.26 C21.1 8.49,13.26 v1(8.25,13.02) ; v1(8.86,9.84) 8.86,9.77 8.38,9.3 8.38,9.16 8.15,8.93 8.07,8.93 7.81,8.66 U1.34
  BOTTOM w0.15: v1(8.25,13.02) 9.46,11.81 9.46,10.35 8.95,9.84 v1(8.86,9.84)
N16839365: length 4.4
  TOP w0.15: U3.17 6.63,18.25 6.35,17.97 6.35,17.85 5.4,16.9 5.25,16.75 3.4,16.75 3.25,16.6 R3.1
N16842652: length 1.4
  TOP w0.15: Y1.3 2.86,6.95 U1.2
N16847933: length 3.3
  TOP w0.15: R8.2 11.3,17 11.05,17.25 11.05,18 10.3,18.75 U3.3
N16848100: length 8.5
  TOP w0.15: U3.15 5.48,19.25 5.4,19.33 5.39,19.33 5.29,19.43 1.93,19.43 1.6,19.1 1.6,16.8 1.89,16.51 R10.1
N16852723: length 3.7
  TOP w0.15: R6.2 11.3,16 10.75,16.55 10.75,17.7 10.2,18.25 U3.2
N16869758: length 11
  TOP w0.33: L6.1 C6.1 10,27.48 arc(10.32,29.12) 11.25,30.5 12.47,31.72 arc(12.86,32.31) ANT1.3
N16876581: length 3.2
  TOP w0.15: R4.2 R9.2 10.5,19 10.25,19.25 U3.4
N169107841: length 2.8
  TOP w0.15: U3.19 7.5,17.38 7.22,17.1 7.05,17.1 7,17.05 6.1,16.15 R7.2

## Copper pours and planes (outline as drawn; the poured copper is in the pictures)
GND on TOP (solid shape): 3.58,35.43 5.58,35.43 5.58,38.07 8.28,38.07 8.28,35.43 10.28,35.43 10.28,38.07 15.28,38.07 15.28,32.75 14.38,32.75 14.38,37.57 13.25,37.57 13.25,32.75 12.75,32.75 12.75,37.57 10.78,37.57 10.78,34.93 7.78,34.93 7.78,37.57 6.08,37.57 6.08,34.93 3.08,34.93 3.08,37.57 1.38,37.57 1.38,34.92 0.88,34.92 0.88,38.07 3.58,38.07
GND on TOP: 2,0.5 0.5,0.5 0.5,2.05 0.5,4.1 2.05,4.1 2.05,6.1 0.5,6.1 0.5,13.2 0.5,33.25 12.6,33.25 12.6,32.55 13.4,32.55 13.4,33.25 15.5,33.25 15.5,13.2 15.5,6.6 14.6,6.6 14.6,4.25 15.5,4.25 15.5,2.05 15.5,0.5 13.2,0.5 ; 24 cut-outs
GND on BOTTOM: 2,0.5 0.5,0.5 0.5,2.05 0.5,15.75 0.5,33.25 15.5,33.25 15.5,15.75 15.5,2.05 15.5,0.5 13.2,0.5 ; 1 cut-out
GND on ANALOGUE GROUND: 2,0.5 0.5,0.5 0.5,2.05 0.5,13.2 0.5,33.25 15.5,33.25 15.5,13.2 15.5,2.05 15.5,0.5 13.2,0.5
GND on DIGITAL GROUND: 2,0.5 0.5,0.5 0.5,2.05 0.5,15.75 0.5,33.25 15.5,33.25 15.5,16.7 15.15,16.7 15.15,15.05 15.5,15.05 15.5,2.05 15.5,0.5 13.2,0.5 ; 1 cut-out

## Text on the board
Ref Des/Silkscreen Bottom: T9 | T2 | T3 | T12 | T13 | T6 | T7 | T4 | T5 | T8 | T10 | T11 | T14 | T15 | T16 | J1 | J2
Ref Des/Silkscreen Top: LAY-46122 Rev A | PCB2467-2 | OM15072-2 | JN5189 | OM15072-K32W
BODY_CENTER: TITRE | TITLE | . | No EVOL | DESSINE/DRAWN | ASCO-SR | REV. | Nbr/Qty | DATE | 18-Nov-2019 | EVOLUTION/CHANGE | M.BAUDRY | VERIFIE/CHECKED | NUMERO DOCUMENT/DOCUMENT NUMBER | DESS./DRAWN | APPROUVE/APPROVED | ..-..-.... | VERIF./CHECKED | PAGE | Austin, TX 78735-8598 | 6501 William Cannon Drive West | SEMICONDUCTORS | 9 | EXTERNAL AMPLIFICATOR MODULE K32W - OM15072-K32W | / | LAY-46122 | A
DEVICE_TYPE_TOP: 4 | LAYER1 - TOP LAYER
DISPLAY_TOP: 7 | LAYER4 - BOTTOM LAYER
COMPVAL_TYPE_TOP: 5 | LAYER 2
TOLERANCE_TOP: 6 | LAYER 3
User.18: 2 | SILKSCREEN TOP
User.19: 8 | SOLDERMASK BOTTOM
User.20: 4 | PASTEMASK BOT | 435
User.22: 1 | PASTEMASK TOP
User.24: 3 | SOLDERMASK TOP
User.25: 9 | OUTLINE
User.43: File. | TOP/BOTTOM
User.45: All rights are reserved. Reproduction in | whole or in part is prohibited without | the written consent of the copyright owner | NXP Semiconductors | 6501 William Cannon Drive West | Austin, TX 78735-8598 | Date | Draw by | Verify | Modifications | SIZE | REV. | IND. | PL. | Date : 18-Nov-2019 | Draw by : SR_ASCO | Checked by:M.BAUDRY | Project : OM15072 | Finition : .... | Material : .... | Protection : .... | Marging : +/-0.1 | Manufact.level : . | Scale : 2.5/1 | Nbr of layers : . | Silkscreen | TOP   :... | BOTTOM:... | 1 | <- VIA | FIGURE | DIAMETRE / HOLESIZE | 0,30 mm (PERCE) | 0,70 mm +0,10 -0,05 | 0,40 mm +0,10 -0,10 | LEGENDE DE PERCAGE / DRILL LEGEND | ALL UNITS ARE IN MILLIMETERS | PLATED | NON-PLATED | Qte / Qty | 460 | 31 | 16 | ASSEMBLY DRAWING TOP OM15072-K32W | EXTERNAL AMPLIFICATOR MODULE | D | C | B | A | 4 | 3 | 2 | A4 | LAY-46122
